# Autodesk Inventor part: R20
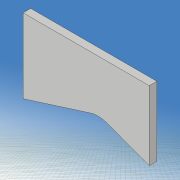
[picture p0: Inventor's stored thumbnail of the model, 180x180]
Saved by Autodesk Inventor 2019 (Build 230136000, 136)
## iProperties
Created: 2021-05
Part Number: R20
Material: 一般
Document SubType Name: Modeling
Designer: kikut
Density: 1 g/cm^3
Appearance: 既定
Mass: 0.0471377 g
Surface Area: 1.80427 cm^2
Volume: 0.0471377 cm^3
Author: kikut
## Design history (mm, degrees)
sketch "スケッチ1"
  geometry: L1 (80, 60)-(-80, 60); L2 (-80, 60)-(-80, -60); L3 (-80, -60)-(80, -60); L4 (80, -60)-(80, 60); L5 (80, 60)-(-80, -60); L6 (-80, 60)-(80, -60); 1 further point
  constraints: 12 end point, 2 midpoint, 2 parallel, 1 horizontal, 1 perpendicular
  dimensions: "d0" = 160 distance of L2.end L3.end; "d1" = 120 distance of L1.end L2.end
extrude "押し出し1" new body sketch "スケッチ1" stored distance "d2" = 0.6; taper "d3" = 0 deg
sketch "スケッチ2"
  geometry: L1 (-140, 0)-(140, 0) reference; L2 (0, -54)-(20, -30); L3 (0, 54)-(20, 30); L4 (0, -3)-(6.514, -3); L5 (6.514, -3)-(16, -6); L6 (16, -6)-(24, -3); L7 (24, -3)-(33.716, -3); L8 (0, 3)-(6.514, 3); L9 (6.514, 3)-(16, 6); L10 (16, 6)-(24, 3); L11 (24, 3)-(33.716, 3); L12 (0, -98)-(0, 98) reference; L13 (-100, -70)-(100, -70); L14 (100, -70)-(100, 70); L15 (100, 70)-(-100, 70); L16 (-100, 70)-(-100, -70); L17 (-100, -70)-(100, 70); L18 (100, -70)-(-100, 70); A1 r 60 centre (54.312, 28.5) between (0, 54) and (0, 3); A2 r 60 centre (54.312, -28.5) between (0, -3) and (0, -54); A3 r 18.111 centre (18, -12) between (20, -30) and (33.716, -3); A4 r 18.111 centre (18, 12) between (33.716, 3) and (20, 30); 1 further point
  constraints: 32 end point, 8 point on circle, 8 symmetric about line, 4 centre point, 3 horizontal, 2 collinear, 2 midpoint, 2 parallel, 1 perpendicular
  dimensions: "d5" = 60 radius of A1; "d6" = 6 distance of L8.start L4.start; "d7" = 108 distance of L3.start L2.start; "d8" = 0 horizontal distance of L3.start L8.start; "d9" = 60 distance of L3.end L2.end; "d10" = 0 horizontal distance of point (0, 0) L3.start; "d11" = 20 horizontal distance of L3.start L3.end; "d12" = 24 distance of A4.centre A3.centre; "d13" = 6 distance of L11.end L7.end; "d14" = 12 distance of L9.end L5.end; "d15" = 16 distance from line of L12 L5.end; "d16" = 24 distance from line of L6.end L12; "d17" = 200 distance of L14.end L15.end; "d18" = 140 distance of L15.end L13.start; "d30" = 18 distance from line of L12 A4.centre
extrude "押し出し2" cut sketch "スケッチ2" stored distance "d19" = 10; taper "d20" = 0 deg
sketch "スケッチ3"
  geometry: L1 (49.705, -17.97)-(33.948, -15.191); L2 (33.948, -15.191)-(34.295, -13.222); L3 (34.295, -13.222)-(50.052, -16); L4 (50.052, -16)-(49.705, -17.97); L5 (49.705, -17.97)-(34.295, -13.222); L6 (33.948, -15.191)-(50.052, -16); L7 (50.052, 16)-(34.295, 13.222); L8 (34.295, 13.222)-(33.948, 15.191); L9 (33.948, 15.191)-(49.705, 17.97); L10 (49.705, 17.97)-(50.052, 16); L11 (50.052, 16)-(33.948, 15.191); L12 (34.295, 13.222)-(49.705, 17.97); L13 (-112, 0)-(112, 0) reference; L14 (0, -84)-(0, 84) reference; 3 further points
  constraints: 24 end point, 4 midpoint, 4 parallel, 2 perpendicular, 2 symmetric about line
  dimensions: "d21" = 2 distance of L3.end L1.start; "d22" = 2 distance of L9.end L7.start; "d23" = 16 distance of L8.end L9.end; "d24" = 42 distance from line of L14 point (42, 15.596); "d26" = 10 deg angle of L7 L13; "d62" = 16 distance from line of L3.end L13
extrude "押し出し3" join sketch "スケッチ3" distance "d27" = 0.6; taper "d28" = 0 deg
fillet "フィレット1" dims "d31" = 2
fillet "フィレット2" dims "d32" = 1
sketch "スケッチ6"
  geometry: L1 (-20, 60)-(80, 60); L2 (80, 60)-(80, -60); L3 (80, -60)-(-20, -60); L4 (-20, -60)-(-20, 60); L5 (-46.168, 0)-(93.832, 0) reference; L6 (0, -84)-(0, 84) reference; L7 (10, 0)-(20, 0); L8 (20, 0)-(20, 10); L9 (20, 10)-(10, 10); L10 (10, 10)-(10, 0); 1 further point
  constraints: 16 end point, 4 parallel, 2 horizontal, 2 perpendicular, 1 other
  dimensions: "d63" = 120 distance of L3.end L1.start; "d64" = 100 distance of L1.start L1.end; "d65" = 20 distance between parallel lines of L6 L4; "d66" = 10 distance of L8.end L9.end; "d73" = 10 distance of L9.end L7.start; "d74" = 0 distance between parallel lines of L7 L5; "d75" = 30 distance between parallel lines of L10 L4
extrude "押し出し4" cut sketch "スケッチ6" stored distance "d70" = 10; taper "d71" = 0 deg
node "ソリッド1"
